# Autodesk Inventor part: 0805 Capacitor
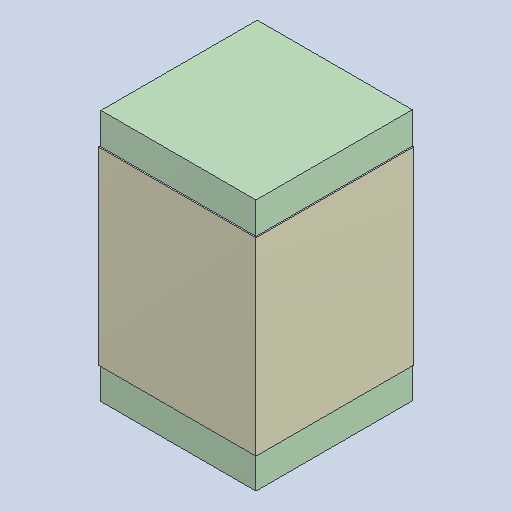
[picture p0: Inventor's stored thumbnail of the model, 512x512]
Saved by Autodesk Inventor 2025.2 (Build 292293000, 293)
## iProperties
Created: 2025-04
Part Number: 0805 Capacitor
Material: Generic
Description: PART--DESC
Document SubType Name: Modeling
Designer: BennF
Density: 1 g/cm^3
Appearance: Default
Author: BennF
Revision Number: NONE
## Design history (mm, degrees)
feature "Solid1"
body "Solid2"
